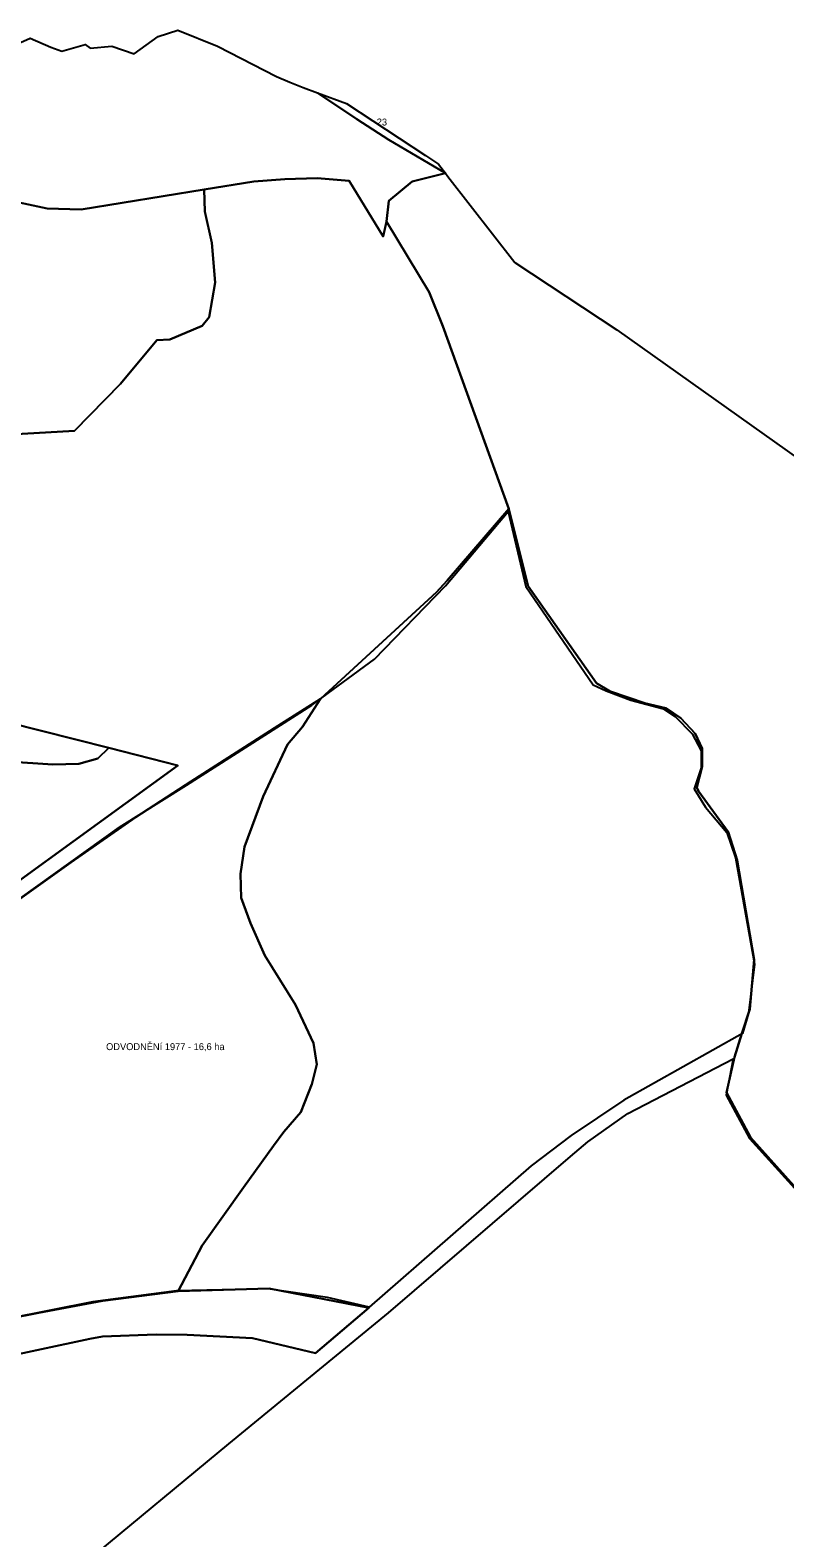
# Model space of a CAD drawing. Extents: x -521621 to -516761, y -1190184 to -1184927.
# Drawn here: x -518086 to -517651, y -1186003 to -1185133 of the extents above; entities that cross this region are included whole.
import ezdxf

# ---------------------------------------------------------------- set-up
doc = ezdxf.new("R2010")
doc.units = 0
doc.layers.add('BPEJ_s', color=7, linetype='Continuous')
doc.layers.add('odvodneni_s', color=7, linetype='Continuous')

msp = doc.modelspace()

# ---------------------------------------------------------------- linework, layer by layer
at = {"layer": 'BPEJ_s'}
for points in [[(-518097.61, -1185142.49), (-518086.36, -1185137.58), (-518074.53, -1185142.78), (-518068.18, -1185145.09), (-518054.61, -1185141.33), (-518051.72, -1185143.36), (-518039.32, -1185142.2), (-518026.33, -1185146.53), (-518012.48, -1185136.71), (-518001.23, -1185132.96), (-517978.22, -1185142.13), (-517944.17, -1185159.75), (-517936.53, -1185162.92), (-517928.88, -1185166.09), (-517920.53, -1185169.16), (-517897.96, -1185184.28), (-517879.43, -1185196.25), (-517846.82, -1185215.4), (-517865.89, -1185220.26), (-517879.44, -1185231.33), (-517880.71, -1185243.39), (-517882.71, -1185252.05), (-517902.38, -1185219.88), (-517920.83, -1185218.31), (-517939.53, -1185218.83), (-517957.4, -1185220.28), (-517986.09, -1185224.9), (-518056.97, -1185236.31), (-518076.55, -1185235.78), (-518129, -1185224.7)], [(-518121.38, -1185367.48), (-518060.92, -1185363.99), (-518034.24, -1185336.9), (-518013.39, -1185311.69), (-518005.77, -1185311.43), (-517987.24, -1185303.41), (-517983.17, -1185298.54), (-517979.63, -1185278.48), (-517981.6, -1185255.6), (-517985.68, -1185237.63), (-517986.09, -1185224.9), (-517957.4, -1185220.28), (-517939.53, -1185218.83), (-517920.83, -1185218.31), (-517902.38, -1185219.88), (-517882.71, -1185252.05), (-517880.71, -1185243.39), (-517856.08, -1185284.02), (-517848.34, -1185303.76), (-517810.19, -1185409.08), (-517845.7, -1185450.39), (-517851.92, -1185457.17), (-517918.87, -1185518.56), (-517943.56, -1185534.23), (-517993.6, -1185566.23), (-518025.47, -1185586.87), (-518063.02, -1185613.04), (-518124.48, -1185656.9)], [(-517618.96, -1185829.18), (-517670.79, -1185771.46), (-517684.5, -1185745.73), (-517679.96, -1185725.29), (-517675.65, -1185711.74), (-517671.19, -1185697.72), (-517668.64, -1185669.04), (-517678.51, -1185611.68), (-517683.61, -1185595.43), (-517700.8, -1185571.85), (-517701.79, -1185569.7), (-517698.67, -1185557.9), (-517698.67, -1185547.27), (-517702.72, -1185538.6), (-517710.91, -1185529.81), (-517719.33, -1185523.99), (-517731.62, -1185521.09), (-517751.5, -1185514.34), (-517759.58, -1185509.52), (-517799.12, -1185453.73), (-517810.19, -1185409.08), (-517848.34, -1185303.76), (-517856.08, -1185284.02), (-517880.71, -1185243.39), (-517879.44, -1185231.33), (-517865.89, -1185220.26), (-517846.82, -1185215.4), (-517845.38, -1185217.32), (-517806.72, -1185266.98), (-517747.77, -1185305.77), (-517642.17, -1185380.83)], [(-518129, -1185224.7), (-518076.55, -1185235.78), (-518056.97, -1185236.31), (-517986.09, -1185224.9), (-517985.68, -1185237.63), (-517981.6, -1185255.6), (-517979.63, -1185278.48), (-517983.17, -1185298.54), (-517987.24, -1185303.41), (-518005.77, -1185311.43), (-518013.39, -1185311.69), (-518034.24, -1185336.9), (-518060.92, -1185363.99), (-518121.38, -1185367.48)], [(-518135.94, -1185905.75), (-518052.06, -1185887.84), (-518044.74, -1185886.51), (-518013.66, -1185885.33), (-517995.76, -1185885.53), (-517958.19, -1185887.3), (-517921.7, -1185896.11), (-517890.96, -1185869.95), (-517948.43, -1185858.75), (-518000.93, -1185860.3), (-517987.24, -1185833.98), (-517963.33, -1185800.43), (-517945.92, -1185776.5), (-517940.11, -1185768.34), (-517930.3, -1185757.05), (-517923.92, -1185740.86), (-517920.98, -1185729.57), (-517922.94, -1185717.3), (-517933.24, -1185695.21), (-517950.9, -1185666.75), (-517959.23, -1185648.1), (-517964.63, -1185633.38), (-517965.12, -1185619.63), (-517962.67, -1185603.93), (-517951.88, -1185574.97), (-517937.83, -1185544.89), (-517929.24, -1185534.73), (-517918.87, -1185518.56), (-517851.92, -1185457.17), (-517845.7, -1185450.39), (-517810.19, -1185409.08), (-517799.12, -1185453.73), (-517759.58, -1185509.52), (-517751.5, -1185514.34), (-517731.62, -1185521.09), (-517719.33, -1185523.99), (-517710.91, -1185529.81), (-517702.72, -1185538.6), (-517698.67, -1185547.27), (-517698.67, -1185557.9), (-517701.79, -1185569.7), (-517700.8, -1185571.85), (-517683.61, -1185595.43), (-517678.51, -1185611.68), (-517668.64, -1185669.04), (-517671.19, -1185697.72), (-517675.65, -1185711.74), (-517679.96, -1185725.29), (-517684.5, -1185745.73), (-517670.79, -1185771.46), (-517618.96, -1185829.18)], [(-518196.61, -1185507.76), (-518041.04, -1185546.97), (-518047.43, -1185553.02), (-518058.24, -1185556.17), (-518073.24, -1185556.51), (-518099.4, -1185554.77)], [(-518122.25, -1185644.81), (-518001.24, -1185557), (-518041.04, -1185546.97), (-518196.61, -1185507.76)], [(-518124.48, -1185656.9), (-518063.02, -1185613.04), (-518025.47, -1185586.87), (-517993.6, -1185566.23), (-517943.56, -1185534.23), (-517918.87, -1185518.56), (-517929.24, -1185534.73), (-517937.83, -1185544.89), (-517951.88, -1185574.97), (-517962.67, -1185603.93), (-517965.12, -1185619.63), (-517964.63, -1185633.38), (-517959.23, -1185648.1), (-517950.9, -1185666.75), (-517933.24, -1185695.21), (-517922.94, -1185717.3), (-517920.98, -1185729.57), (-517923.92, -1185740.86), (-517930.3, -1185757.05), (-517940.11, -1185768.34), (-517945.92, -1185776.5), (-517963.33, -1185800.43), (-517987.24, -1185833.98), (-518000.93, -1185860.3), (-518044.39, -1185865.85), (-518081.39, -1185872.69), (-518194.51, -1185895.07)], [(-518099.4, -1185554.77), (-518073.24, -1185556.51), (-518058.24, -1185556.17), (-518047.43, -1185553.02), (-518041.04, -1185546.97), (-518001.24, -1185557), (-518122.25, -1185644.81)], [(-518194.51, -1185895.07), (-518081.39, -1185872.69), (-518044.39, -1185865.85), (-518000.93, -1185860.3), (-517948.43, -1185858.75), (-517890.96, -1185869.95), (-517921.7, -1185896.11), (-517958.19, -1185887.3), (-517995.76, -1185885.53), (-518013.66, -1185885.33), (-518044.74, -1185886.51), (-518052.06, -1185887.84), (-518135.94, -1185905.75)]]:
    msp.add_lwpolyline(points, dxfattribs=at)
msp.add_lwpolyline([(-517920.53, -1185169.16), (-517903.78, -1185175.33), (-517858.18, -1185205.33), (-517850.69, -1185210.26), (-517846.82, -1185215.4), (-517879.43, -1185196.25), (-517897.96, -1185184.28)], close=True, dxfattribs=at)
at = {"layer": 'odvodneni_s'}
for points in [[(-518092.02, -1185633.55), (-518034.79, -1185592.7), (-517996.12, -1185568.37), (-517923.92, -1185522.21), (-517887.74, -1185495.7), (-517846.73, -1185453.44), (-517810.55, -1185410.56), (-517800.34, -1185453.9), (-517761.47, -1185510.5), (-517753.95, -1185514.09), (-517739.8, -1185519.46), (-517720.99, -1185524.48), (-517714.18, -1185528.78), (-517704.33, -1185538.81), (-517699.13, -1185548.66), (-517699.13, -1185558.51), (-517703.25, -1185570.51), (-517696.62, -1185581.08), (-517684.44, -1185595.77), (-517679.43, -1185610.28), (-517668.5, -1185671.72), (-517671.9, -1185700.03), (-517675.31, -1185711.67), (-517743.74, -1185750.19), (-517774.19, -1185770.43), (-517797.3, -1185787.98), (-517890.75, -1185869.44), (-517914.78, -1185864.02), (-517949.17, -1185858.96), (-518001.93, -1185860.13), (-518050.21, -1185866.49), (-518150.32, -1185886.28)], [(-518053.59, -1186016), (-517971.74, -1185948.32), (-517879.63, -1185872.83), (-517774.64, -1185782.59), (-517764.66, -1185774.21), (-517741.52, -1185757.86), (-517680.72, -1185726.31), (-517684.76, -1185747.17), (-517671.24, -1185772.28), (-517619.33, -1185829.45)]]:
    msp.add_lwpolyline(points, dxfattribs=at)

# ---------------------------------------------------------------- texts
at = {"layer": 'BPEJ_s'}
msp.add_text('23', height=4, dxfattribs=at).set_placement((-517886.4, -1185187.95))
at = {"layer": 'odvodneni_s'}
msp.add_text('ODVODNĚNí 1977 - 16,6 ha', height=4, dxfattribs=at).set_placement((-518042.6, -1185721.25))

doc.saveas('drawing.dxf')
